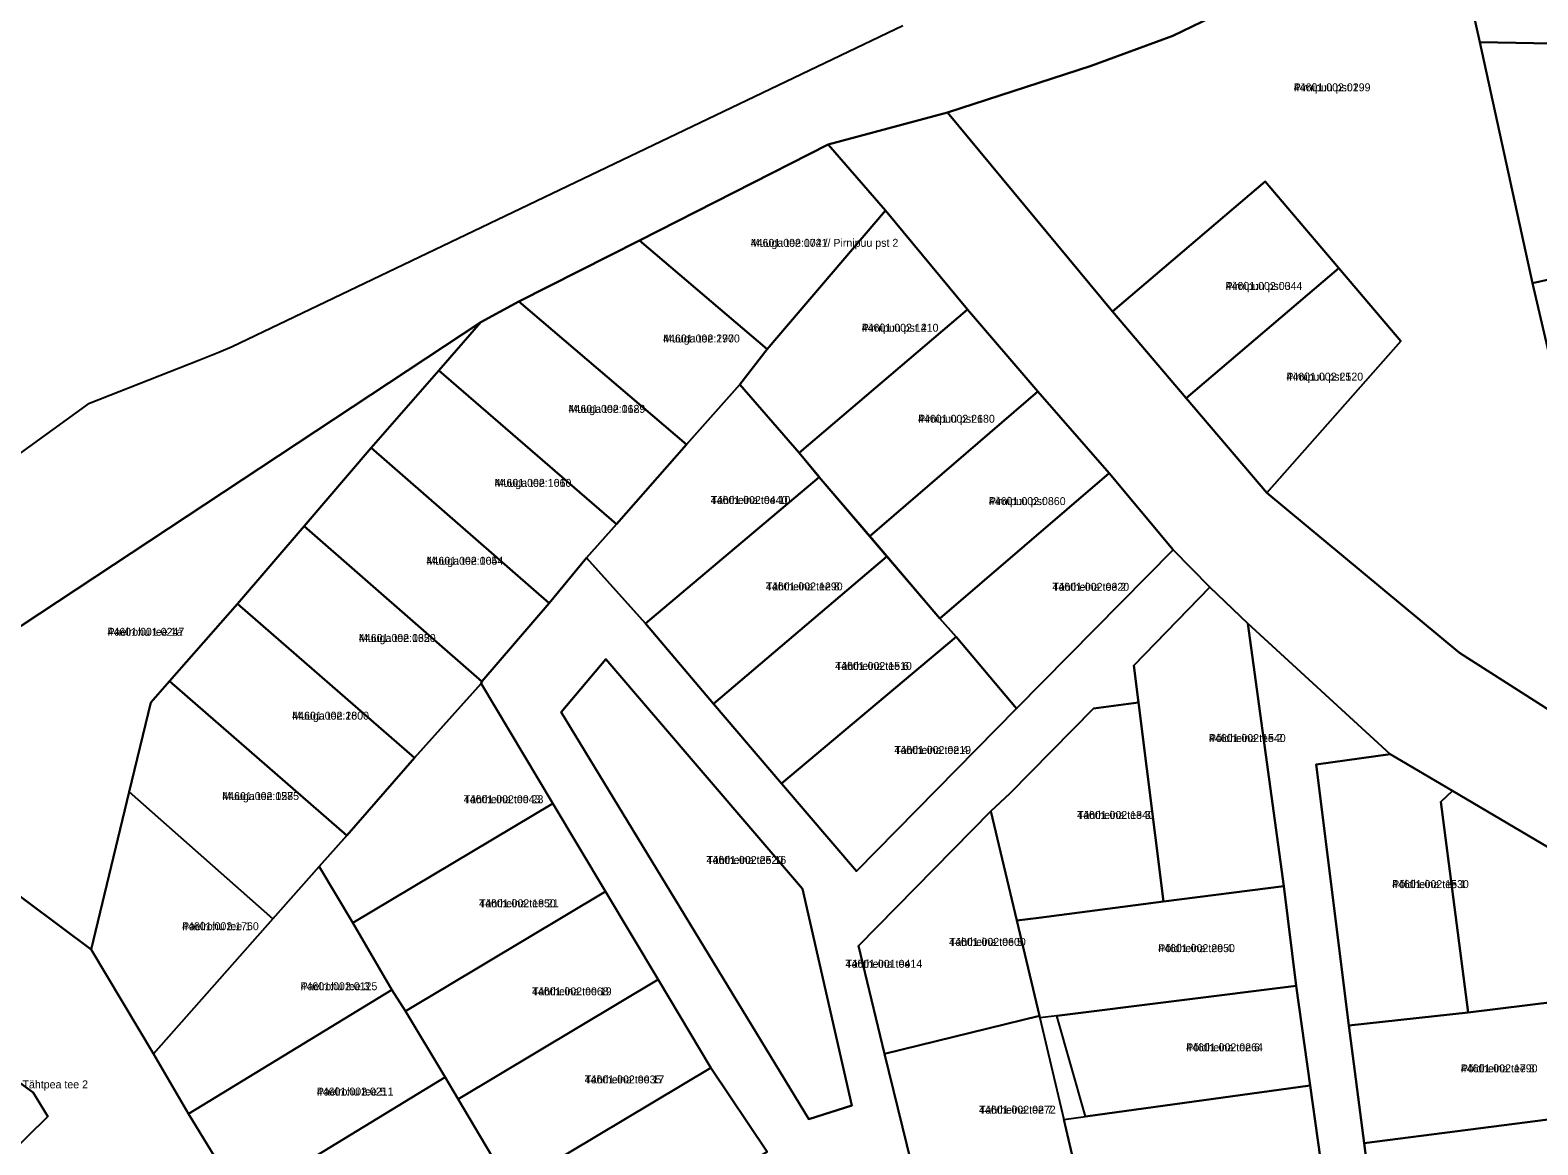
# Model space of a CAD drawing. Extents: x 551843 to 558501, y 6589003 to 6595718.
# Drawn here: x 552375.1 to 552659.9, y 6593731.8 to 6593942.4 of the extents above; entities that cross this region are included whole.
import ezdxf

# ---------------------------------------------------------------- set-up
doc = ezdxf.new("R2010")
doc.units = 0
for name, color, linetype in [('L_AADRESS', 7, 'Continuous'), ('PIIR', 7, 'Continuous'), ('TUNNUS', 7, 'Continuous')]:
    doc.layers.add(name, color=color, linetype=linetype)

msp = doc.modelspace()

# ---------------------------------------------------------------- linework, layer by layer
at = {"layer": 'PIIR'}
for points in [[(552548.38, 6593926.81), (552575.56, 6593935.66), (552590.98, 6593941.34), (552601.95, 6593946.6), (552613.73, 6593954.16), (552625.24, 6593964.01), (552640.04, 6593981.38), (552645.64, 6593955.03), (552649, 6593940.14), (552658.94, 6593894.58), (552667.67, 6593857.02), (552668.71, 6593850.94), (552675.72, 6593820.25), (552679.24, 6593802.97), (552645.15, 6593824.74), (552608.7, 6593854.94), (552627.36, 6593876.07), (552634.04, 6593883.65), (552622.34, 6593897.4), (552608.41, 6593913.77), (552600.79, 6593907.29), (552579.54, 6593889.2)], [(552669.31, 6593939.75), (552678.48, 6593899), (552658.94, 6593894.58), (552649, 6593940.14)], [(552525.85, 6593920.77), (552536.66, 6593908.31), (552514.32, 6593882.12), (552490.2, 6593902.67)], [(552614.72, 6593890.92), (552593.47, 6593872.84), (552579.54, 6593889.2), (552600.79, 6593907.29), (552608.41, 6593913.77), (552622.34, 6593897.4)], [(552552.18, 6593889.61), (552520.34, 6593862.51), (552509.16, 6593875.43), (552514.32, 6593882.12), (552536.66, 6593908.31)], [(552490.2, 6593902.67), (552514.32, 6593882.12), (552509.16, 6593875.43), (552499.11, 6593864.08), (552467.41, 6593891.09)], [(552678.48, 6593899), (552681.3, 6593899.64), (552689.81, 6593861.97), (552667.67, 6593857.02), (552658.94, 6593894.58)], [(552593.47, 6593872.84), (552614.72, 6593890.92), (552622.34, 6593897.4), (552634.04, 6593883.65), (552627.36, 6593876.07), (552608.7, 6593854.94)], [(552460.2, 6593887.22), (552467.41, 6593891.09), (552499.11, 6593864.08), (552485.83, 6593849.07), (552452.27, 6593878.1)], [(552524.17, 6593857.95), (552524.12, 6593858.01), (552520.34, 6593862.51), (552552.18, 6593889.61), (552565.49, 6593874.09), (552533.69, 6593846.8)], [(552368.34, 6593782.27), (552348.98, 6593813.8), (552460.2, 6593887.22), (552452.27, 6593878.1), (552439.53, 6593863.46), (552426.86, 6593848.66), (552414.28, 6593833.98), (552401.4, 6593819.39), (552397.87, 6593815.35), (552393.81, 6593798.44), (552386.59, 6593768.69)], [(552485.83, 6593849.07), (552480.18, 6593842.68), (552473.11, 6593834.09), (552439.53, 6593863.46), (552452.27, 6593878.1)], [(552480.18, 6593842.68), (552485.83, 6593849.07), (552499.11, 6593864.08), (552509.16, 6593875.43), (552520.34, 6593862.51), (552524.17, 6593857.95), (552491.36, 6593830.28)], [(552578.94, 6593858.7), (552546.93, 6593831.22), (552533.69, 6593846.8), (552565.49, 6593874.09)], [(552439.53, 6593863.46), (552473.11, 6593834.09), (552460.39, 6593819.3), (552426.86, 6593848.66)], [(552578.94, 6593858.7), (552591, 6593844.18), (552561.46, 6593814.22), (552550.06, 6593827.77), (552546.93, 6593831.22)], [(552491.36, 6593830.28), (552524.17, 6593857.95), (552536.95, 6593842.96), (552504.21, 6593815.11)], [(552460.39, 6593819.3), (552460.26, 6593818.94), (552447.67, 6593804.92), (552414.28, 6593833.98), (552426.86, 6593848.66)], [(552504.21, 6593815.11), (552536.95, 6593842.96), (552546.93, 6593831.22), (552550.06, 6593827.77), (552517.02, 6593800.05)], [(552583.62, 6593822.33), (552597.96, 6593837.11), (552605.11, 6593830.26), (552611.96, 6593780.63), (552589.18, 6593777.73), (552584.48, 6593815.38)], [(552414.28, 6593833.98), (552447.67, 6593804.92), (552434.89, 6593790.24), (552401.4, 6593819.39)], [(552517.02, 6593800.05), (552550.06, 6593827.77), (552561.46, 6593814.22), (552531.23, 6593783.49)], [(552483.85, 6593823.53), (552520.98, 6593780.15), (552530.32, 6593739.19), (552522.18, 6593736.62), (552475.4, 6593813.53)], [(552475.4, 6593813.53), (552522.18, 6593736.62), (552530.32, 6593739.19), (552520.98, 6593780.15), (552483.85, 6593823.53)], [(552393.81, 6593798.44), (552397.87, 6593815.35), (552401.4, 6593819.39), (552434.89, 6593790.24), (552429.68, 6593784.34), (552420.94, 6593774.45)], [(552436.04, 6593773.7), (552429.68, 6593784.34), (552434.89, 6593790.24), (552447.67, 6593804.92), (552460.26, 6593818.94), (552473.81, 6593796.29)], [(552556.56, 6593794.8), (552560.15, 6593798.15), (552575.95, 6593814.21), (552584.48, 6593815.38), (552589.18, 6593777.73), (552565.63, 6593774.67), (552561.48, 6593774.13)], [(552643.8, 6593798.67), (552641.63, 6593796.6), (552646.76, 6593756.77), (552624.25, 6593754.29), (552618.03, 6593803.63), (552632.06, 6593805.56)], [(552386.59, 6593768.69), (552393.81, 6593798.44), (552420.94, 6593774.45), (552398.39, 6593748.95)], [(552643.8, 6593798.67), (552677.65, 6593778.72), (552663.55, 6593758.85), (552646.76, 6593756.77), (552641.63, 6593796.6)], [(552483.77, 6593779.65), (552446.01, 6593757.04), (552443.41, 6593761.06), (552436.04, 6593773.7), (552473.81, 6593796.29)], [(552565.77, 6593756.12), (552536.52, 6593748.99), (552531.59, 6593769.38), (552556.56, 6593794.8), (552561.48, 6593774.13)], [(552398.39, 6593748.95), (552420.94, 6593774.45), (552429.68, 6593784.34), (552436.04, 6593773.7), (552443.41, 6593761.06), (552404.98, 6593737.65)], [(552483.77, 6593779.65), (552493.73, 6593763), (552455.97, 6593740.4), (552453.48, 6593744.53), (552446.01, 6593757.04)], [(552565.63, 6593774.67), (552589.18, 6593777.73), (552611.96, 6593780.63), (552614.29, 6593761.79), (552569.03, 6593756.14), (552565.86, 6593755.74), (552565.77, 6593756.12), (552561.48, 6593774.13)], [(552375.65, 6593741.65), (552378.41, 6593737.13), (552362.62, 6593721.62), (552333.53, 6593751.21), (552345.78, 6593763.27)], [(552493.73, 6593763), (552503.69, 6593746.35), (552465.93, 6593723.75), (552463.36, 6593727.89), (552455.97, 6593740.4)], [(552569.03, 6593756.14), (552614.29, 6593761.79), (552616.94, 6593742.99), (552574.46, 6593737.11)], [(552415.05, 6593721.12), (552404.98, 6593737.65), (552443.41, 6593761.06), (552446.01, 6593757.04), (552453.48, 6593744.53)], [(552624.25, 6593754.29), (552646.76, 6593756.77), (552663.55, 6593758.85), (552666.19, 6593739.43), (552666.3, 6593737.11), (552627.12, 6593732.09)], [(552544.13, 6593717.92), (552536.52, 6593748.99), (552565.77, 6593756.12), (552565.86, 6593755.74), (552570.38, 6593736.55), (552572.15, 6593729.03), (552547.97, 6593719.47)], [(552424.83, 6593704.63), (552415.05, 6593721.12), (552453.48, 6593744.53), (552455.97, 6593740.4), (552463.36, 6593727.89)], [(552503.69, 6593746.35), (552514.35, 6593730.44), (552476.69, 6593707.93), (552474.09, 6593711.76), (552465.93, 6593723.75)], [(552572.15, 6593729.03), (552570.38, 6593736.55), (552574.46, 6593737.11), (552616.94, 6593742.99), (552619.81, 6593722.34), (552579.05, 6593717.11), (552576.21, 6593716.75), (552573.34, 6593729.4)], [(552627.12, 6593732.09), (552666.3, 6593737.11), (552668.87, 6593717.03), (552630.18, 6593708.17)]]:
    msp.add_lwpolyline(points, close=True, dxfattribs=at)
for points in [[(552864.99, 6593935.18), (552827.53, 6593936.06), (552811.72, 6593936.55), (552790.81, 6593937.04), (552771.81, 6593937.49), (552749.75, 6593938.01), (552729.85, 6593938.48), (552720.71, 6593938.38), (552692.54, 6593939.13), (552669.31, 6593939.75), (552649, 6593940.14), (552645.64, 6593955.03)], [(552601.95, 6593946.6), (552590.98, 6593941.34), (552575.56, 6593935.66), (552548.38, 6593926.81), (552525.85, 6593920.77), (552490.2, 6593902.67), (552467.41, 6593891.09), (552460.2, 6593887.22), (552348.98, 6593813.8)], [(552310.94, 6593817.34), (552386.27, 6593871.92), (552406.96, 6593880.05), (552410.7, 6593881.56), (552413.26, 6593882.59), (552539.95, 6593943.24)], [(552677.65, 6593778.72), (552643.8, 6593798.67), (552632.06, 6593805.56), (552605.11, 6593830.26), (552597.96, 6593837.11), (552591, 6593844.18), (552578.94, 6593858.7), (552565.49, 6593874.09), (552552.18, 6593889.61), (552536.66, 6593908.31), (552525.85, 6593920.77), (552548.38, 6593926.81), (552579.54, 6593889.2), (552593.47, 6593872.84), (552608.7, 6593854.94), (552645.15, 6593824.74), (552679.24, 6593802.97)], [(552514.35, 6593730.44), (552503.69, 6593746.35), (552493.73, 6593763), (552483.77, 6593779.65), (552473.81, 6593796.29), (552460.26, 6593818.94), (552460.39, 6593819.3), (552473.11, 6593834.09), (552480.18, 6593842.68), (552491.36, 6593830.28), (552504.21, 6593815.11), (552517.02, 6593800.05), (552531.23, 6593783.49), (552561.46, 6593814.22), (552591, 6593844.18), (552597.96, 6593837.11), (552583.62, 6593822.33), (552584.48, 6593815.38), (552575.95, 6593814.21), (552560.15, 6593798.15), (552556.56, 6593794.8), (552531.59, 6593769.38), (552536.52, 6593748.99), (552544.13, 6593717.92)], [(552619.81, 6593722.34), (552616.94, 6593742.99), (552614.29, 6593761.79), (552611.96, 6593780.63), (552605.11, 6593830.26), (552632.06, 6593805.56), (552618.03, 6593803.63), (552624.25, 6593754.29), (552627.12, 6593732.09), (552630.18, 6593708.17)], [(552368.34, 6593782.27), (552386.59, 6593768.69), (552398.39, 6593748.95), (552404.98, 6593737.65), (552415.05, 6593721.12)], [(552362.62, 6593721.62), (552378.41, 6593737.13), (552375.65, 6593741.65), (552345.78, 6593763.27)]]:
    msp.add_lwpolyline(points, dxfattribs=at)

# ---------------------------------------------------------------- texts
at = {"layer": 'L_AADRESS'}
for s, p in [('Pirnipuu pst 1', (552613.81, 6593930.83)), ('Muuga tee 172 // Pirnipuu pst 2', (552511.22, 6593901.45)), ('Pirnipuu pst 3', (552600.94, 6593893.3)), ('Pirnipuu pst 4', (552532.19, 6593885.41)), ('Muuga tee 170', (552494.66, 6593883.38)), ('Pirnipuu pst 5', (552612.42, 6593876.17)), ('Muuga tee 168', (552476.8, 6593870.08)), ('Pirnipuu pst 6', (552542.83, 6593868.21)), ('Muuga tee 166', (552462.83, 6593856.1)), ('Tähtheina tee 10', (552503.65, 6593852.86)), ('Pirnipuu pst 8', (552556.21, 6593852.65)), ('Muuga tee 164', (552449.97, 6593841.38)), ('Tähtheina tee 8', (552514.08, 6593836.53)), ('Tähtheina tee 2', (552568.21, 6593836.46)), ('Paelrohu tee 1a', (552389.69, 6593827.96)), ('Muuga tee 162', (552437.19, 6593826.79)), ('Tähtheina tee 6', (552527.16, 6593821.51)), ('Muuga tee 160', (552424.59, 6593812.11)), ('Tähtheina tee 4', (552538.34, 6593805.63)), ('Põldheina tee 2', (552597.79, 6593807.88)), ('Muuga tee 158', (552411.37, 6593796.92)), ('Tähtheina tee 23', (552456.99, 6593796.32)), ('Tähtheina tee 3', (552572.87, 6593793.35)), ('Tähtheina tee 16', (552502.86, 6593784.85)), ('Põldheina tee 1', (552632.39, 6593780.28)), ('Tähtheina tee 21', (552459.89, 6593776.66)), ('Paelrohu tee 1', (552403.77, 6593772.33)), ('Tähtheina tee 5', (552548.68, 6593769.37)), ('Põldheina tee 4', (552588.2, 6593768.18)), ('Tähtheina tee', (552529.11, 6593765.23)), ('Paelrohu tee 3', (552426.17, 6593760.99)), ('Tähtheina tee 19', (552469.88, 6593760.02)), ('Põldheina tee 6', (552593.48, 6593749.45)), ('Tähtheina tee 17', (552479.83, 6593743.38)), ('Põldheina tee 3', (552645.38, 6593745.47)), ('Paelrohu tee 4 // Tähtpea tee 2', (552358.35, 6593742.45)), ('Paelrohu tee 5', (552429.23, 6593741.09)), ('Tähtheina tee 7', (552554.34, 6593737.66))]:
    msp.add_text(s, height=1.5, dxfattribs=at).set_placement(p)
at = {"layer": 'TUNNUS'}
for s, p in [('44601:002:0299', (552613.81, 6593930.83)), ('44601:002:0041', (552511.22, 6593901.45)), ('44601:002:0044', (552600.94, 6593893.3)), ('44601:002:1210', (552532.19, 6593885.41)), ('44601:002:2970', (552494.66, 6593883.38)), ('44601:002:2120', (552612.42, 6593876.17)), ('44601:002:0129', (552476.8, 6593870.08)), ('44601:002:2180', (552542.83, 6593868.21)), ('44601:002:1010', (552462.83, 6593856.1)), ('44601:002:0440', (552503.65, 6593852.86)), ('44601:002:0860', (552556.21, 6593852.65)), ('44601:002:0054', (552449.97, 6593841.38)), ('44601:002:1290', (552514.08, 6593836.53)), ('44601:002:0320', (552568.21, 6593836.46)), ('44601:001:0247', (552389.69, 6593827.96)), ('44601:002:0350', (552437.19, 6593826.79)), ('44601:002:1510', (552527.16, 6593821.51)), ('44601:002:2800', (552424.59, 6593812.11)), ('44601:002:0219', (552538.34, 6593805.63)), ('44601:002:1540', (552597.79, 6593807.88)), ('44601:002:0275', (552411.37, 6593796.92)), ('44601:002:0043', (552456.99, 6593796.32)), ('44601:002:1340', (552572.87, 6593793.35)), ('44601:002:2520', (552502.86, 6593784.85)), ('44601:002:1530', (552632.39, 6593780.28)), ('44601:002:1850', (552459.89, 6593776.66)), ('44601:002:1760', (552403.77, 6593772.33)), ('44601:002:0600', (552548.68, 6593769.37)), ('44601:002:2950', (552588.2, 6593768.18)), ('44601:001:0414', (552529.11, 6593765.23)), ('44601:002:0125', (552426.17, 6593760.99)), ('44601:002:0068', (552469.88, 6593760.02)), ('44601:002:0264', (552593.48, 6593749.45)), ('44601:002:0035', (552479.83, 6593743.38)), ('44601:002:1790', (552645.38, 6593745.47)), ('44601:002:0211', (552429.23, 6593741.09)), ('44601:002:0272', (552554.34, 6593737.66))]:
    msp.add_text(s, height=1.5, dxfattribs=at).set_placement(p)

doc.saveas('drawing.dxf')
